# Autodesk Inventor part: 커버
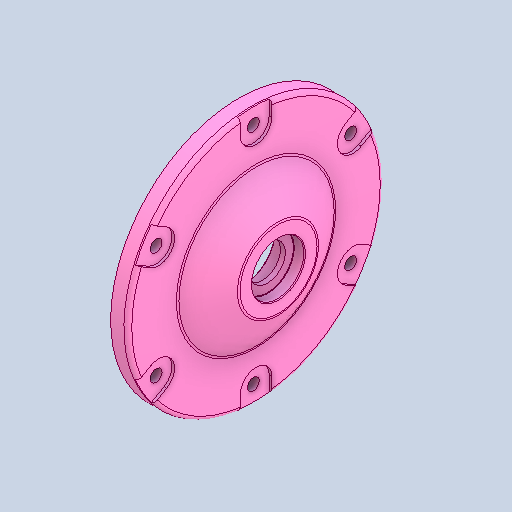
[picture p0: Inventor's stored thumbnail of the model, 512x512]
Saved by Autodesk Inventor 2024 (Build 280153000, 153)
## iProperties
Created: 2025-11
Part Number: 커버
Material: 알루미늄 6061
Document SubType Name: Modeling
Designer: Eud07
Density: 2.7 g/cm^3
Appearance: 기본값
Author: jhkim
Sending System: Autodesk Inventor 2026
Preprocessor: ST-DEVELOPER v20.1
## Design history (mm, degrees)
node "커버1"
node "솔리드2"
node "솔리드1"
